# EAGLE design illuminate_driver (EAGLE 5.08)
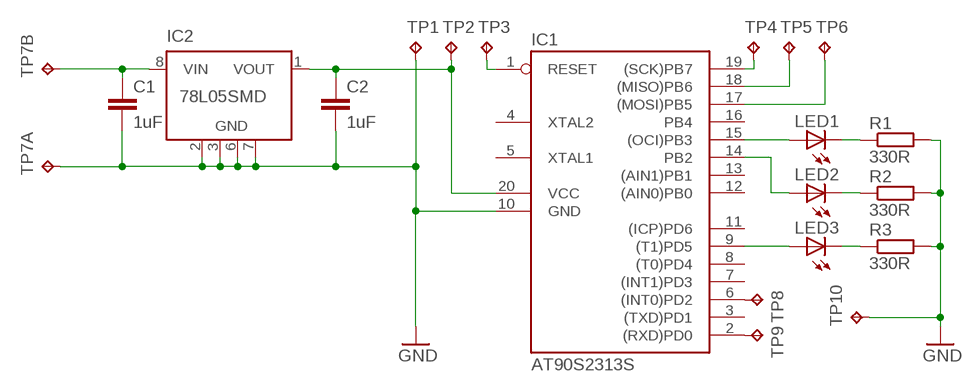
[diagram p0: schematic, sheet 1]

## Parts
C1  1uF  C-EUC1206  [C1206]
C2  1uF  C-EUC1206  [C1206]
IC1  AT90S2313S  [SO20L]
IC2  78L05SMD  [SO08]
LED1  LED3MM  [LED3MM]
LED2  LED3MM  [LED3MM]
LED3  LED3MM  [LED3MM]
R1  330R  R-EU_M1206  [M1206]
R2  330R  R-EU_M1206  [M1206]
R3  330R  R-EU_M1206  [M1206]
TP1  TPTP15SQ  [TP15SQ]
TP2  TPTP15SQ  [TP15SQ]
TP3  TPTP15R  [TP15R]
TP4  TPTP15R  [TP15R]
TP5  TPTP15R  [TP15R]
TP6  TPTP15R  [TP15R]
TP7  TP2P2-38-20  [P2-38-20]
TP8  TPTP15R  [TP15R]
TP9  TPTP15R  [TP15R]
TP10  TPTP15R  [TP15R]

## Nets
GND: C1.2 C2.2 IC1.10(GND) IC2.2(GND) IC2.3(GND) IC2.6(GND) IC2.7(GND) R1.2 R2.2 R3.2 TP1.TP TP7.TP-1 TP10.TP
N$3: IC1.1(RESET) TP3.TP
N$4: IC1.19((SCK)PB7) TP4.TP
N$5: IC1.18((MISO)PB6) TP5.TP
N$6: IC1.17((MOSI)PB5) TP6.TP
N$7: IC1.15((OCI)PB3) LED1.A
N$8: IC1.14(PB2) LED2.A
N$9: IC1.9((T1)PD5) LED3.A
N$10: LED1.K(C) R1.1
N$11: LED2.K(C) R2.1
N$12: LED3.K(C) R3.1
N$13: C1.1 IC2.8(VIN) TP7.TP-2
N$14: C2.1 IC1.20(VCC) IC2.1(VOUT) TP2.TP
N$19: IC1.6((INT0)PD2) TP8.TP
N$20: IC1.2((RXD)PD0) TP9.TP
Unconnected: IC1.3((TXD)PD1) IC1.4(XTAL2) IC1.5(XTAL1) IC1.7((INT1)PD3) IC1.8((T0)PD4) IC1.11((ICP)PD6) IC1.12((AIN0)PB0) IC1.13((AIN1)PB1) IC1.16(PB4) IC2.4(NC) IC2.5(NC)

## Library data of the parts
C1 C2 = rcl:C-EU: CAPACITOR, European symbol
IC1 = atmel:AT90S2313: MICROCONTROLLER 2 Kbytes FLASH 128 bytes SRAM 128 bytes EEPROM UART
IC2 = linear:78L*SMD: Positive VOLTAGE REGULATOR
LED1-LED3 = led:LED: LED
R1-R3 = rcl:R-EU_: RESISTOR, European symbol
TP1-TP6 TP8-TP10 = testpad:TP: Test pad
TP7 = testpad:TP2: Test pad

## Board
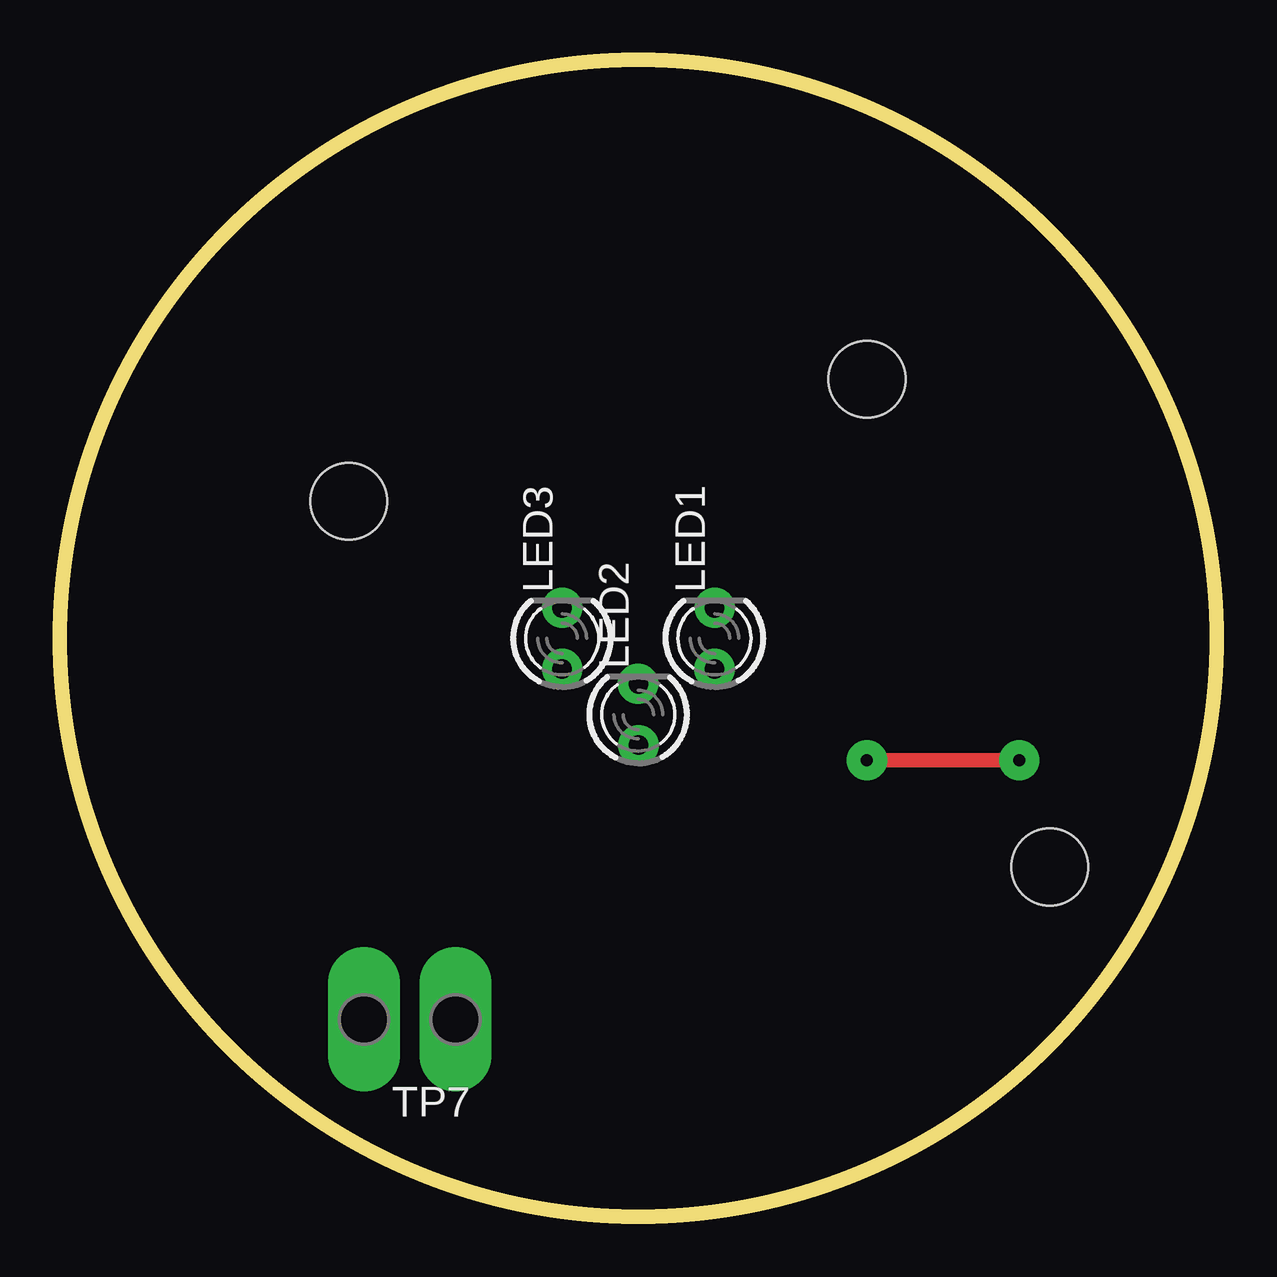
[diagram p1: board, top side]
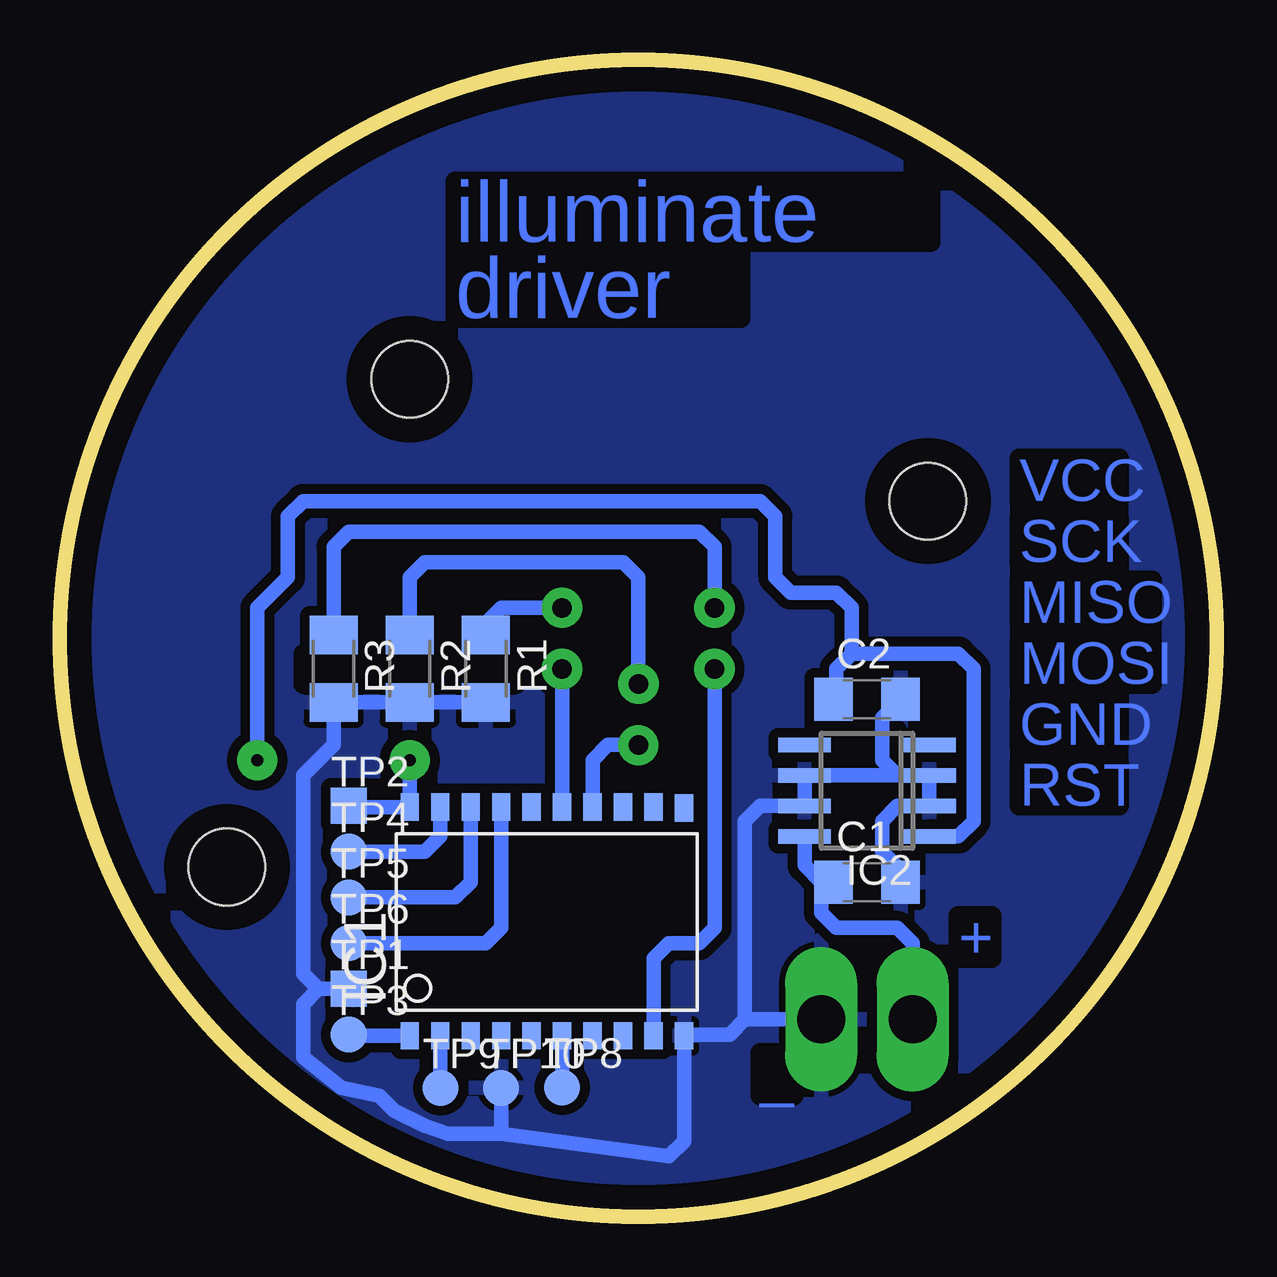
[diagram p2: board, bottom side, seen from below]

Size 48.19 x 48.19 mm. Coordinates in mm from the lower left corner, seen from the top.
Outline: circle at 24.1,24.1 radius 24.1
Copper layers (1*16): Top 0.035mm / dielectric 1.5mm / Bottom 0.035mm
Design rules "default": minimum track width 10mil, minimum drill 24mil, track to track 8mil, track to pad 8mil, pad to pad 8mil, via to via 8mil, smd to smd 8mil, copper to edge 40mil, drill to drill 8mil, minimum pad ring 10mil, minimum via ring 8mil, stop-mask expansion 4mil, vias tented up to drill 0mil, thermal gap 10mil
Holes 3.2 mm at 12.03,29.81 41.24,14.57 33.62,34.89
bRestrict: area 10.8,20.3 to 12,22.8; area 13.9,20.9 to 15.2,22.2; area 13.3,15.2 to 16.5,20.3; area 13.9,12.7 to 15.2,15.2; area 12.7,14.6 to 13.9,15.2; area 34.3,8.2 to 35.5,10.8; area 29.2,22.2 to 38.1,23.5

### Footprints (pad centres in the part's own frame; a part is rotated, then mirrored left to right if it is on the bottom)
C1206 = smd 1.6 x 1.8: 1 -1.4,0; 2 1.4,0
SO20L = smd 0.762 x 1.143: 1 -5.08,-5.131; 2 -3.81,-5.131; 3 -2.54,-5.131; 4 -1.27,-5.131; 5 0,-5.131; 6 1.27,-5.131; 7 2.54,-5.131; 8 3.81,-5.131; 9 5.08,-5.131; 10 6.35,-5.131; 11 6.35,4.369; 12 5.08,4.394; 13 3.81,4.394; 14 2.54,4.394; 15 1.27,4.394; 16 0,4.394; 17 -1.27,4.394; 18 -2.54,4.394; 19 -3.81,4.394; 20 -5.08,4.394
SO08 = smd 0.6 x 2.2: 1 -1.905,-2.6; 2 -0.635,-2.6; 3 0.635,-2.6; 4 1.905,-2.6; 5 1.905,2.6; 6 0.635,2.6; 7 -0.635,2.6; 8 -1.905,2.6
LED3MM = drill 0.813 octagon: A -1.27,0; K 1.27,0
M1206 = smd 1.6 x 2: 1 -1.4,0; 2 1.4,0
TP15SQ = smd 1.5 x 1.5: TP 0,0
TP15R = smd 1.5 x 1.5: TP 0,0
P2-38-20 = drill 2.007 pad 2.54 long: TP-1 -1.905,0; TP-2 1.905,0

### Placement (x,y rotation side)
C1  14.57,13.94 0 bottom
C2  14.57,21.56 0 bottom
IC1  28.54,12.67 0 bottom
IC2  14.57,17.75 90 bottom
LED1  27.27,24.1 90 top
LED2  24.1,20.92 90 top
LED3  20.92,24.1 90 top
R1  30.45,22.83 270 bottom
R2  33.62,22.83 270 bottom
R3  36.8,22.83 270 bottom
TP1  36.16,9.49 0 bottom
TP2  36.16,17.11 0 bottom
TP3  36.16,7.59 0 bottom
TP4  36.16,15.21 0 bottom
TP5  36.16,13.3 0 bottom
TP6  36.16,11.4 0 bottom
TP7  14.57,8.22 180 top
TP8  27.27,5.38 0 bottom
TP9  32.34,5.36 0 bottom
TP10  29.81,5.36 0 bottom

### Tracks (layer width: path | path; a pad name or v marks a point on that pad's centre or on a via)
GND
  Bottom 0.61: IC2.3 IC2.6 IC2.7 19.02,17.11 19.65,16.48 19.65,8.22 | IC2.3 IC2.2 13.3,17.11 13.94,16.48 13.94,15.21 13.17,14.44 C1.2 | IC2.3 13.3,18.38 13.94,19.02 13.94,20.79 C2.2 | R1.2 R2.2 R3.2 36.8,19.65 38.07,18.38 38.07,10.13 37.43,9.49 | 37.43,9.49 TP1.TP | 37.43,9.49 38.07,8.86 38.07,6.63 36.48,5.36 34.89,5.05 34.26,4.41 32.99,3.78 32.03,3.46 29.81,3.46 | 19.65,8.22 20.29,7.59 22.14,7.59 IC1.10 22.19,3.14 22.83,2.51 29.81,3.46 | TP7.TP-1 19.65,8.22 | 29.81,3.46 TP10.TP
  pour Bottom (isolate 0.406): 23.46,49.5 24.73,49.5 arc-90 49.5,24.73 arc-90 23.46,-1.3 22.83,-1.3 arc-90 -1.3,22.83 -1.3,24.73 arc-90
N$1  (via drill 0.6 pad 1.68)
  other vias: 24.09,22.21
N$2  (via drill 0.6 pad 1.68)
  other vias: 24.1,19.65
N$3
  Bottom 0.61: IC1.1 36.11,7.54 TP3.TP
N$4
  Bottom 0.61: IC1.19 32.35,15.84 32.99,15.21 TP4.TP
N$5
  Bottom 0.61: IC1.18 31.08,13.94 31.72,13.3 TP5.TP
N$6
  Bottom 0.61: IC1.17 29.81,12.03 30.45,11.4 TP6.TP
N$7
  Bottom 0.61: IC1.15 LED1.A
N$8
  Bottom 0.61: IC1.14 26,19.02 25.37,19.65 LED2.A
N$9
  Bottom 0.61: LED3.A 20.92,12.03 21.56,11.4 22.83,11.4 23.46,10.76 IC1.9
N$10
  Bottom 0.61: LED1.K 29.81,25.37 30.45,24.73 R1.1
N$11
  Bottom 0.61: LED2.K 24.1,26.64 24.73,27.27 32.99,27.27 33.62,26.64 R2.1
N$12
  Bottom 0.61: LED3.K 20.92,27.91 21.56,28.54 36.16,28.54 36.8,27.91 R3.1
N$13
  Bottom 0.61: IC2.8 17.17,14.63 16.48,13.94 | 16.48,13.94 C1.1 | TP7.TP-2 12.67,11.4 13.3,12.03 15.84,12.03 16.48,12.67 16.48,13.94
N$14  (via drill 0.5 pad 1.68)
  Top 0.61: v39.97,19.02 v33.62,19.02
  Bottom 0.61: IC2.1 10.76,15.84 10.13,16.48 10.13,22.83 10.76,23.46 15.21,23.46 | 15.21,23.46 15.84,22.83 15.84,21.69 C2.1 | TP2.TP 36.11,17.06 IC1.20 v33.62,19.02 | v39.97,19.02 39.97,25.37 38.7,26.64 38.7,29.18 38.07,29.81 19.02,29.81 18.38,29.18 18.38,26.64 17.75,26 15.84,26 15.21,25.37 15.21,23.46
N$15  (via drill 0.6 pad 1.68)
  other vias: 27.27,22.82
N$16  (via drill 0.6 pad 1.68)
  other vias: 27.28,25.37
N$17  (via drill 0.6 pad 1.68)
  other vias: 20.92,25.37
N$18  (via drill 0.6 pad 1.68)
  other vias: 20.93,22.82
N$19
  Bottom 0.61: TP8.TP 27.27,5.07 IC1.6
N$20
  Bottom 0.61: TP9.TP 32.35,5.05 IC1.2

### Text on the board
Bottom: illuminate | driver | VCC | SCK | MISO | MOSI | GND | RST | + | _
